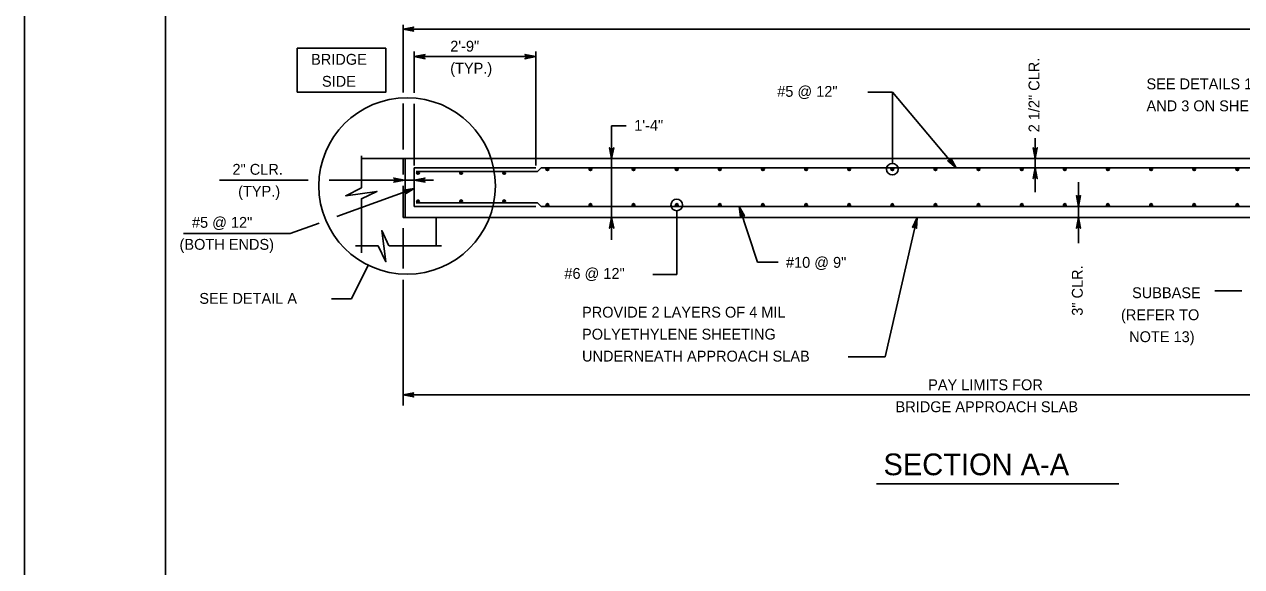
# Model space of a CAD drawing. Extents: x 638079 to 640019, y 297691 to 298879.
# Drawn here: x 638274 to 638610.1, y 298481.4 to 298631.2 of the extents above; entities that cross this region are included whole.
import ezdxf

# ---------------------------------------------------------------- set-up
doc = ezdxf.new("R2010")
doc.units = 0
doc.layers.add('1', color=7, linetype='Continuous')
doc.layers.add('PLT-BNDY', color=7, linetype='Continuous')

msp = doc.modelspace()

# ---------------------------------------------------------------- linework, layer by layer
at = {"layer": '1'}
for p, q in [((638378.58, 298612.43), (638378.58, 298631.05)), ((638378.58, 298629.92), (638683.38, 298629.92)), ((638381.69, 298612.27), (638381.69, 298623.72)), ((638381.69, 298622.3), (638415.22, 298622.3)), ((638415.22, 298592.27), (638415.22, 298623.72)), ((638506.87, 298612.45), (638513.67, 298612.45)), ((638513.67, 298592.82), (638513.67, 298612.45)), ((638513.67, 298612.45), (638531.33, 298591.6)), ((638378.58, 298596.65), (638378.58, 298609.34)), ((638381.69, 298592.27), (638381.69, 298609.26)), ((638436.18, 298571.65), (638436.18, 298603.19)), ((638436.18, 298603.19), (638440.21, 298603.19)), ((638553.14, 298584.86), (638553.14, 298599.76)), ((638367.16, 298594.87), (638367.16, 298586.04)), ((638367.16, 298594.14), (638378.58, 298594.14)), ((638378.58, 298594.14), (638683.38, 298594.14)), ((638378.58, 298594.14), (638378.58, 298589.78)), ((638379.14, 298594.14), (638379.14, 298577.89)), ((638381.69, 298591.6), (638381.69, 298580.94)), ((638381.69, 298591.6), (638415.22, 298591.6)), ((638415.73, 298590.59), (638416.75, 298591.6)), ((638416.75, 298591.6), (638646.3, 298591.6)), ((638513.67, 298591.22), (638513.67, 298591.22)), ((638327.94, 298588.21), (638352.35, 298588.21)), ((638358.2, 298588.21), (638387.02, 298588.21)), ((638382.2, 298590.59), (638415.73, 298590.59)), ((638565.03, 298570.76), (638565.03, 298587.65)), ((638360.26, 298578.1), (638381.69, 298585.86)), ((638378.58, 298586.59), (638378.58, 298577.89)), ((638367.16, 298583.11), (638367.16, 298568.1)), ((638381.69, 298580.94), (638415.22, 298580.94)), ((638382.2, 298581.95), (638415.73, 298581.95)), ((638415.73, 298581.95), (638416.75, 298580.94)), ((638416.75, 298580.94), (638646.3, 298580.94)), ((638454.14, 298581.32), (638454.14, 298581.32)), ((638476.43, 298565.49), (638471.38, 298580.94)), ((638378.58, 298577.89), (638683.38, 298577.89)), ((638387.73, 298577.89), (638387.73, 298570.03)), ((638454.14, 298562.1), (638454.14, 298579.72)), ((638511.7, 298539.4), (638520.49, 298577.89)), ((638347.43, 298573.44), (638355.4, 298576.33)), ((638378.58, 298563.77), (638378.58, 298574.93)), ((638317.94, 298573.44), (638347.43, 298573.44)), ((638365.43, 298570.03), (638371.71, 298570.03)), ((638374.71, 298570.03), (638389.17, 298570.03)), ((638364.38, 298555.35), (638368.91, 298564.71)), ((638476.43, 298565.49), (638482.14, 298565.49)), ((638378.58, 298525.95), (638378.58, 298560.64)), ((638447.58, 298562.1), (638454.14, 298562.1)), ((638602.7, 298557.59), (638610.12, 298557.59)), ((638358.83, 298555.35), (638364.38, 298555.35)), ((638501.45, 298539.4), (638511.7, 298539.4)), ((638378.58, 298528.84), (638715.82, 298528.84)), ((638509.31, 298504.23), (638576.22, 298504.23))]:
    msp.add_line(p, q, dxfattribs=at)
for points in [[(639099.03, 298300.23), (639099.03, 298864.23), (638313.03, 298864.23), (638313.03, 298300.23), (639099.03, 298300.23), (639099.03, 298326.59), (638899.03, 298326.59), (638899.03, 298391.26), (639099.03, 298391.26), (639099.03, 298420.23), (638899.03, 298420.23), (638899.03, 298300.23), (638977.83, 298300.23), (638977.83, 298326.59), (638977.83, 298300.23), (639054.83, 298300.23), (639054.83, 298326.59), (639054.83, 298314.27), (639099.03, 298314.27)], [(638378.58, 298629.92), (638381.56, 298630.48), (638381.45, 298630.4), (638381.33, 298630.32), (638381.28, 298630.22), (638381.22, 298630.12), (638381.2, 298630.02), (638381.18, 298629.92), (638381.2, 298629.82), (638381.22, 298629.72), (638381.28, 298629.62), (638381.33, 298629.52), (638381.45, 298629.44), (638381.56, 298629.36), (638378.58, 298629.92), (638381.45, 298629.44), (638381.33, 298629.52), (638378.58, 298629.92), (638381.28, 298629.62), (638381.22, 298629.72), (638378.58, 298629.92), (638381.2, 298629.82), (638381.18, 298629.92), (638378.58, 298629.92), (638381.2, 298630.02), (638381.22, 298630.12), (638378.58, 298629.92), (638381.28, 298630.22), (638381.33, 298630.32), (638378.58, 298629.92), (638381.45, 298630.4)], [(638381.69, 298622.3), (638384.68, 298622.86), (638384.56, 298622.78), (638384.45, 298622.7), (638384.39, 298622.6), (638384.33, 298622.5), (638384.31, 298622.4), (638384.29, 298622.3), (638384.31, 298622.2), (638384.33, 298622.1), (638384.39, 298622), (638384.45, 298621.9), (638384.56, 298621.82), (638384.68, 298621.74), (638381.69, 298622.3), (638384.56, 298621.82), (638384.45, 298621.9), (638381.69, 298622.3), (638384.39, 298622), (638384.33, 298622.1), (638381.69, 298622.3), (638384.31, 298622.2), (638384.29, 298622.3), (638381.69, 298622.3), (638384.31, 298622.4), (638384.33, 298622.5), (638381.69, 298622.3), (638384.39, 298622.6), (638384.45, 298622.7), (638381.69, 298622.3), (638384.56, 298622.78)], [(638415.22, 298622.3), (638412.24, 298621.74), (638412.36, 298621.82), (638412.47, 298621.9), (638412.53, 298622), (638412.59, 298622.1), (638412.61, 298622.2), (638412.62, 298622.3), (638412.61, 298622.4), (638412.59, 298622.5), (638412.53, 298622.6), (638412.47, 298622.7), (638412.36, 298622.78), (638412.24, 298622.86), (638415.22, 298622.3), (638412.36, 298622.78), (638412.47, 298622.7), (638415.22, 298622.3), (638412.53, 298622.6), (638412.59, 298622.5), (638415.22, 298622.3), (638412.61, 298622.4), (638412.62, 298622.3), (638415.22, 298622.3), (638412.61, 298622.2), (638412.59, 298622.1), (638415.22, 298622.3), (638412.53, 298622), (638412.47, 298621.9), (638415.22, 298622.3), (638412.36, 298621.82)], [(638436.18, 298594.14), (638435.62, 298597.13), (638435.7, 298597.01), (638435.78, 298596.9), (638435.88, 298596.84), (638435.98, 298596.78), (638436.08, 298596.76), (638436.18, 298596.74), (638436.28, 298596.76), (638436.38, 298596.78), (638436.48, 298596.84), (638436.58, 298596.9), (638436.66, 298597.01), (638436.74, 298597.13), (638436.18, 298594.14), (638436.66, 298597.01), (638436.58, 298596.9), (638436.18, 298594.14), (638436.48, 298596.84), (638436.38, 298596.78), (638436.18, 298594.14), (638436.28, 298596.76), (638436.18, 298596.74), (638436.18, 298594.14), (638436.08, 298596.76), (638435.98, 298596.78), (638436.18, 298594.14), (638435.88, 298596.84), (638435.78, 298596.9), (638436.18, 298594.14), (638435.7, 298597.01)], [(638531.33, 298591.6), (638528.97, 298593.52), (638529.24, 298593.45), (638529.47, 298593.48), (638529.65, 298593.59), (638529.78, 298593.74), (638529.85, 298593.96), (638529.83, 298594.24), (638531.33, 298591.6), (638529.85, 298593.96), (638529.78, 298593.74), (638531.33, 298591.6), (638529.65, 298593.59), (638529.47, 298593.48), (638531.33, 298591.6), (638529.24, 298593.45)], [(638553.14, 298594.14), (638552.58, 298597.13), (638552.74, 298596.9), (638552.94, 298596.78), (638553.14, 298596.74), (638553.34, 298596.78), (638553.54, 298596.9), (638553.7, 298597.13), (638553.14, 298594.14), (638553.54, 298596.9), (638553.34, 298596.78), (638553.14, 298594.14), (638553.14, 298596.74), (638552.94, 298596.78), (638553.14, 298594.14), (638552.74, 298596.9)], [(638553.14, 298591.6), (638553.7, 298588.62), (638553.54, 298588.85), (638553.34, 298588.97), (638553.14, 298589), (638552.94, 298588.97), (638552.74, 298588.85), (638552.58, 298588.62), (638553.14, 298591.6), (638552.74, 298588.85), (638552.94, 298588.97), (638553.14, 298591.6), (638553.14, 298589), (638553.34, 298588.97), (638553.14, 298591.6), (638553.54, 298588.85)], [(638378.99, 298588.21), (638376.01, 298587.65), (638376.12, 298587.73), (638376.24, 298587.81), (638376.29, 298587.91), (638376.35, 298588.01), (638376.37, 298588.11), (638376.39, 298588.21), (638376.37, 298588.31), (638376.35, 298588.41), (638376.29, 298588.51), (638376.24, 298588.61), (638376.12, 298588.69), (638376.01, 298588.77), (638378.99, 298588.21), (638376.12, 298588.69), (638376.24, 298588.61), (638378.99, 298588.21), (638376.29, 298588.51), (638376.35, 298588.41), (638378.99, 298588.21), (638376.37, 298588.31), (638376.39, 298588.21), (638378.99, 298588.21), (638376.37, 298588.11), (638376.35, 298588.01), (638378.99, 298588.21), (638376.29, 298587.91), (638376.24, 298587.81), (638378.99, 298588.21), (638376.12, 298587.73)], [(638381.69, 298588.21), (638384.68, 298588.77), (638384.56, 298588.69), (638384.45, 298588.61), (638384.39, 298588.51), (638384.33, 298588.41), (638384.31, 298588.31), (638384.29, 298588.21), (638384.31, 298588.11), (638384.33, 298588.01), (638384.39, 298587.91), (638384.45, 298587.81), (638384.56, 298587.73), (638384.68, 298587.65), (638381.69, 298588.21), (638384.56, 298587.73), (638384.45, 298587.81), (638381.69, 298588.21), (638384.39, 298587.91), (638384.33, 298588.01), (638381.69, 298588.21), (638384.31, 298588.11), (638384.29, 298588.21), (638381.69, 298588.21), (638384.31, 298588.31), (638384.33, 298588.41), (638381.69, 298588.21), (638384.39, 298588.51), (638384.45, 298588.61), (638381.69, 298588.21), (638384.56, 298588.69)], [(638367.16, 298586.04), (638362.75, 298583.88), (638371.38, 298585.06), (638367.16, 298583.05)], [(638381.69, 298585.86), (638379.08, 298584.32), (638379.16, 298584.43), (638379.24, 298584.55), (638379.26, 298584.66), (638379.29, 298584.78), (638379.27, 298584.88), (638379.25, 298584.98), (638379.2, 298585.07), (638379.15, 298585.15), (638379.06, 298585.23), (638378.97, 298585.3), (638378.84, 298585.34), (638378.7, 298585.37), (638381.69, 298585.86), (638378.84, 298585.34), (638378.97, 298585.3), (638381.69, 298585.86), (638379.06, 298585.23), (638379.15, 298585.15), (638381.69, 298585.86), (638379.2, 298585.07), (638379.25, 298584.98), (638381.69, 298585.86), (638379.27, 298584.88), (638379.29, 298584.78), (638381.69, 298585.86), (638379.26, 298584.66), (638379.24, 298584.55), (638381.69, 298585.86), (638379.16, 298584.43)], [(638471.38, 298580.94), (638472.84, 298578.28), (638472.73, 298578.36), (638472.62, 298578.44), (638472.5, 298578.47), (638472.39, 298578.49), (638472.29, 298578.48), (638472.19, 298578.46), (638472.1, 298578.42), (638472.01, 298578.37), (638471.93, 298578.28), (638471.86, 298578.2), (638471.82, 298578.06), (638471.78, 298577.93), (638471.38, 298580.94), (638471.82, 298578.06), (638471.86, 298578.2), (638471.38, 298580.94), (638471.93, 298578.28), (638472.01, 298578.37), (638471.38, 298580.94), (638472.1, 298578.42), (638472.19, 298578.46), (638471.38, 298580.94), (638472.29, 298578.48), (638472.39, 298578.49), (638471.38, 298580.94), (638472.5, 298578.47), (638472.62, 298578.44), (638471.38, 298580.94), (638472.73, 298578.36)], [(638565.03, 298580.94), (638564.47, 298583.92), (638564.63, 298583.69), (638564.83, 298583.57), (638565.03, 298583.54), (638565.23, 298583.57), (638565.43, 298583.69), (638565.59, 298583.92), (638565.03, 298580.94), (638565.43, 298583.69), (638565.23, 298583.57), (638565.03, 298580.94), (638565.03, 298583.54), (638564.83, 298583.57), (638565.03, 298580.94), (638564.63, 298583.69)], [(638436.18, 298577.89), (638436.74, 298574.91), (638436.66, 298575.02), (638436.58, 298575.14), (638436.48, 298575.19), (638436.38, 298575.25), (638436.28, 298575.27), (638436.18, 298575.29), (638436.08, 298575.27), (638435.98, 298575.25), (638435.88, 298575.19), (638435.78, 298575.14), (638435.7, 298575.02), (638435.62, 298574.91), (638436.18, 298577.89), (638435.7, 298575.02), (638435.78, 298575.14), (638436.18, 298577.89), (638435.88, 298575.19), (638435.98, 298575.25), (638436.18, 298577.89), (638436.08, 298575.27), (638436.18, 298575.29), (638436.18, 298577.89), (638436.28, 298575.27), (638436.38, 298575.25), (638436.18, 298577.89), (638436.48, 298575.19), (638436.58, 298575.14), (638436.18, 298577.89), (638436.66, 298575.02)], [(638520.49, 298577.89), (638520.37, 298574.86), (638520.32, 298574.99), (638520.27, 298575.12), (638520.19, 298575.2), (638520.1, 298575.28), (638520.01, 298575.31), (638519.91, 298575.35), (638519.81, 298575.36), (638519.71, 298575.36), (638519.6, 298575.33), (638519.49, 298575.29), (638519.39, 298575.2), (638519.28, 298575.1), (638520.49, 298577.89), (638519.39, 298575.2), (638519.49, 298575.29), (638520.49, 298577.89), (638519.6, 298575.33), (638519.71, 298575.36), (638520.49, 298577.89), (638519.81, 298575.36), (638519.91, 298575.35), (638520.49, 298577.89), (638520.01, 298575.31), (638520.1, 298575.28), (638520.49, 298577.89), (638520.19, 298575.2), (638520.27, 298575.12), (638520.49, 298577.89), (638520.32, 298574.99)], [(638565.03, 298577.89), (638565.59, 298574.91), (638565.43, 298575.14), (638565.23, 298575.25), (638565.03, 298575.29), (638564.83, 298575.25), (638564.63, 298575.14), (638564.47, 298574.91), (638565.03, 298577.89), (638564.63, 298575.14), (638564.83, 298575.25), (638565.03, 298577.89), (638565.03, 298575.29), (638565.23, 298575.25), (638565.03, 298577.89), (638565.43, 298575.14)], [(638371.71, 298570.03), (638373.87, 298565.63), (638372.7, 298574.25), (638374.7, 298570.03)], [(638378.58, 298528.84), (638381.56, 298529.4), (638381.45, 298529.32), (638381.33, 298529.24), (638381.28, 298529.14), (638381.22, 298529.04), (638381.2, 298528.94), (638381.18, 298528.84), (638381.2, 298528.74), (638381.22, 298528.64), (638381.28, 298528.54), (638381.33, 298528.44), (638381.45, 298528.36), (638381.56, 298528.28), (638378.58, 298528.84), (638381.45, 298528.36), (638381.33, 298528.44), (638378.58, 298528.84), (638381.28, 298528.54), (638381.22, 298528.64), (638378.58, 298528.84), (638381.2, 298528.74), (638381.18, 298528.84), (638378.58, 298528.84), (638381.2, 298528.94), (638381.22, 298529.04), (638378.58, 298528.84), (638381.28, 298529.14), (638381.33, 298529.24), (638378.58, 298528.84), (638381.45, 298529.32)]]:
    msp.add_lwpolyline(points, dxfattribs=at)
msp.add_lwpolyline([(638349.4, 298612.45), (638373.79, 298612.45), (638373.79, 298624.64), (638349.4, 298624.64)], close=True, dxfattribs=at)
for centre, radius in [((638379.69, 298586.58), 24.38), ((638418.43, 298591.22), 0.381), ((638418.43, 298591.22), 0.286), ((638418.43, 298591.22), 0.19), ((638418.43, 298591.22), 0.0952), ((638430.33, 298591.22), 0.381), ((638430.33, 298591.22), 0.286), ((638430.33, 298591.22), 0.19), ((638430.33, 298591.22), 0.0952), ((638442.24, 298591.22), 0.381), ((638442.24, 298591.22), 0.286), ((638442.24, 298591.22), 0.19), ((638442.24, 298591.22), 0.0952), ((638454.14, 298591.22), 0.381), ((638454.14, 298591.22), 0.286), ((638454.14, 298591.22), 0.19), ((638454.14, 298591.22), 0.0952), ((638466.05, 298591.22), 0.381), ((638466.05, 298591.22), 0.286), ((638466.05, 298591.22), 0.19), ((638466.05, 298591.22), 0.0952), ((638477.95, 298591.22), 0.381), ((638477.95, 298591.22), 0.286), ((638477.95, 298591.22), 0.19), ((638477.95, 298591.22), 0.0952), ((638489.86, 298591.22), 0.381), ((638489.86, 298591.22), 0.286), ((638489.86, 298591.22), 0.19), ((638489.86, 298591.22), 0.0952), ((638501.77, 298591.22), 0.381), ((638501.77, 298591.22), 0.286), ((638501.77, 298591.22), 0.19), ((638501.77, 298591.22), 0.0952), ((638513.67, 298591.22), 1.6), ((638513.67, 298591.22), 0.381), ((638513.67, 298591.22), 0.286), ((638513.67, 298591.22), 0.19), ((638513.67, 298591.22), 0.0952), ((638525.58, 298591.22), 0.381), ((638525.58, 298591.22), 0.286), ((638525.58, 298591.22), 0.19), ((638525.58, 298591.22), 0.0952), ((638537.48, 298591.22), 0.381), ((638537.48, 298591.22), 0.286), ((638537.48, 298591.22), 0.19), ((638537.48, 298591.22), 0.0952), ((638549.39, 298591.22), 0.381), ((638549.39, 298591.22), 0.286), ((638549.39, 298591.22), 0.19), ((638549.39, 298591.22), 0.0952), ((638561.29, 298591.22), 0.381), ((638561.29, 298591.22), 0.286), ((638561.29, 298591.22), 0.19), ((638561.29, 298591.22), 0.0952), ((638573.2, 298591.22), 0.381), ((638573.2, 298591.22), 0.286), ((638573.2, 298591.22), 0.19), ((638573.2, 298591.22), 0.0952), ((638585.1, 298591.22), 0.381), ((638585.1, 298591.22), 0.286), ((638585.1, 298591.22), 0.19), ((638585.1, 298591.22), 0.0952), ((638597.01, 298591.22), 0.381), ((638597.01, 298591.22), 0.286), ((638597.01, 298591.22), 0.19), ((638597.01, 298591.22), 0.0952), ((638608.92, 298591.22), 0.381), ((638608.92, 298591.22), 0.286), ((638608.92, 298591.22), 0.19), ((638608.92, 298591.22), 0.0952), ((638382.71, 298590.21), 0.381), ((638382.71, 298590.21), 0.286), ((638382.71, 298590.21), 0.19), ((638382.71, 298590.21), 0.0952), ((638394.62, 298590.21), 0.381), ((638394.62, 298590.21), 0.286), ((638394.62, 298590.21), 0.19), ((638394.62, 298590.21), 0.0952), ((638406.52, 298590.21), 0.381), ((638406.52, 298590.21), 0.286), ((638406.52, 298590.21), 0.19), ((638406.52, 298590.21), 0.0952), ((638382.71, 298582.33), 0.381), ((638382.71, 298582.33), 0.286), ((638382.71, 298582.33), 0.19), ((638382.71, 298582.33), 0.0952), ((638394.62, 298582.33), 0.381), ((638394.62, 298582.33), 0.286), ((638394.62, 298582.33), 0.19), ((638394.62, 298582.33), 0.0952), ((638406.52, 298582.33), 0.381), ((638406.52, 298582.33), 0.286), ((638406.52, 298582.33), 0.19), ((638406.52, 298582.33), 0.0952), ((638418.43, 298581.32), 0.381), ((638418.43, 298581.32), 0.286), ((638418.43, 298581.32), 0.19), ((638418.43, 298581.32), 0.0952), ((638430.33, 298581.32), 0.381), ((638430.33, 298581.32), 0.286), ((638430.33, 298581.32), 0.19), ((638430.33, 298581.32), 0.0952), ((638442.24, 298581.32), 0.381), ((638442.24, 298581.32), 0.286), ((638442.24, 298581.32), 0.19), ((638442.24, 298581.32), 0.0952), ((638454.14, 298581.32), 1.6), ((638454.14, 298581.32), 0.381), ((638454.14, 298581.32), 0.286), ((638454.14, 298581.32), 0.19), ((638454.14, 298581.32), 0.0952), ((638466.05, 298581.32), 0.381), ((638466.05, 298581.32), 0.286), ((638466.05, 298581.32), 0.19), ((638466.05, 298581.32), 0.0952), ((638477.95, 298581.32), 0.381), ((638477.95, 298581.32), 0.286), ((638477.95, 298581.32), 0.19), ((638477.95, 298581.32), 0.0952), ((638489.86, 298581.32), 0.381), ((638489.86, 298581.32), 0.286), ((638489.86, 298581.32), 0.19), ((638489.86, 298581.32), 0.0952), ((638501.77, 298581.32), 0.381), ((638501.77, 298581.32), 0.286), ((638501.77, 298581.32), 0.19), ((638501.77, 298581.32), 0.0952), ((638513.67, 298581.32), 0.381), ((638513.67, 298581.32), 0.286), ((638513.67, 298581.32), 0.19), ((638513.67, 298581.32), 0.0952), ((638525.58, 298581.32), 0.381), ((638525.58, 298581.32), 0.286), ((638525.58, 298581.32), 0.19), ((638525.58, 298581.32), 0.0952), ((638537.48, 298581.32), 0.381), ((638537.48, 298581.32), 0.286), ((638537.48, 298581.32), 0.19), ((638537.48, 298581.32), 0.0952), ((638549.39, 298581.32), 0.381), ((638549.39, 298581.32), 0.286), ((638549.39, 298581.32), 0.19), ((638549.39, 298581.32), 0.0952), ((638561.29, 298581.32), 0.381), ((638561.29, 298581.32), 0.286), ((638561.29, 298581.32), 0.19), ((638561.29, 298581.32), 0.0952), ((638573.2, 298581.32), 0.381), ((638573.2, 298581.32), 0.286), ((638573.2, 298581.32), 0.19), ((638573.2, 298581.32), 0.0952), ((638585.1, 298581.32), 0.381), ((638585.1, 298581.32), 0.286), ((638585.1, 298581.32), 0.19), ((638585.1, 298581.32), 0.0952), ((638597.01, 298581.32), 0.381), ((638597.01, 298581.32), 0.286), ((638597.01, 298581.32), 0.19), ((638597.01, 298581.32), 0.0952), ((638608.92, 298581.32), 0.381), ((638608.92, 298581.32), 0.286), ((638608.92, 298581.32), 0.19), ((638608.92, 298581.32), 0.0952)]:
    msp.add_circle(centre, radius, dxfattribs=at)
at = {"layer": 'PLT-BNDY'}
msp.add_lwpolyline([(638274.03, 298879.23), (639115.03, 298879.23), (639115.03, 298285.23), (638274.03, 298285.23)], close=True, dxfattribs=at)

# ---------------------------------------------------------------- texts
at = {"layer": '1'}
for s, height, p in [(' 2\'-9"', 3, (638390.5, 298623.69)), ('BRIDGE', 3, (638353.2, 298620.06)), ('(TYP.)', 3, (638391.61, 298617.62)), ('SIDE', 3, (638356.2, 298613.99)), ('#5 @ 12"', 3, (638481.89, 298611.2)), ('SEE DETAILS 1, 2', 3, (638583.84, 298613.28)), ('AND 3 ON SHEET 3', 3, (638583.84, 298607.21)), ('1\'-4"', 3, (638442.41, 298601.81)), ('2" CLR.', 3, (638331.49, 298589.67)), ('(TYP.)', 3, (638333.06, 298583.6)), ('#5 @ 12"', 3, (638320.31, 298575.01)), ('(BOTH ENDS)', 3, (638316.88, 298568.94)), ('#6 @ 12"', 3, (638423.13, 298560.91)), ('#10 @ 9"', 3, (638484.31, 298563.96)), ('SUBBASE', 3, (638579.86, 298555.57)), ('SEE DETAIL A', 3, (638322.34, 298554.01)), ('PROVIDE 2 LAYERS OF 4 MIL', 3, (638428, 298550.2)), ('(REFER TO', 3, (638576.8, 298549.49)), ('POLYETHYLENE SHEETING', 3, (638428, 298544.13)), ('NOTE 13)', 3, (638579.05, 298543.42)), ('UNDERNEATH APPROACH SLAB', 3, (638428, 298538.06)), ('PAY LIMITS FOR', 3, (638523.56, 298530.14)), ('BRIDGE APPROACH SLAB', 3, (638514.56, 298524.07)), ('SECTION A-A', 6, (638511.22, 298506.65))]:
    msp.add_text(s, height=height, dxfattribs=at).set_placement(p)
for s, p in [('2 1/2" CLR.', (638554.28, 298601.4)), ('3" CLR.', (638566.24, 298550.72))]:
    msp.add_text(s, height=3, rotation=90, dxfattribs=at).set_placement(p)

doc.saveas('drawing.dxf')
